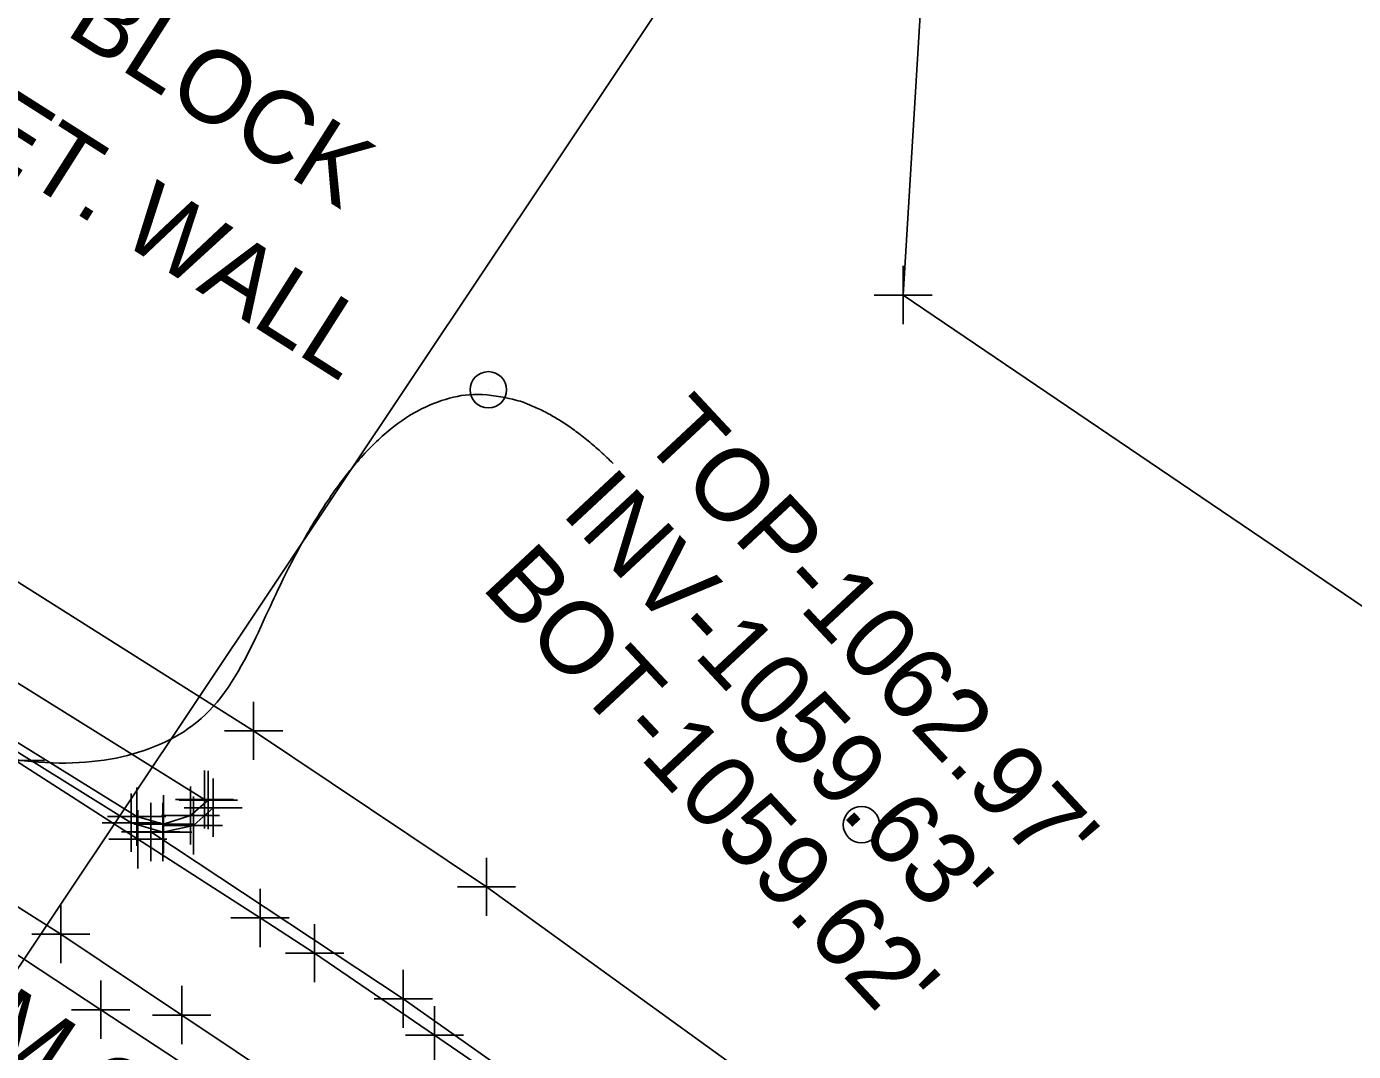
# Model space of a CAD drawing. Extents: x 0 to 1944463, y 0 to 420651.
# Drawn here: x 1942891.8 to 1942983.1, y 417799.1 to 417869.6 of the extents above; entities that cross this region are included whole.
import ezdxf

# ---------------------------------------------------------------- set-up
doc = ezdxf.new("R2010")
doc.units = 0
for name, color, linetype in [('SUR - DRG - Storm Sewer Text', 7, 'Continuous'), ('SUR - DTM - Breaklines', 7, 'Continuous'), ('SUR - DTM - Breaklines - Points - Locators', 7, 'Continuous'), ('SUR - DTM - Spot Points - Locators', 7, 'Continuous'), ('SUR - NON-TRAN - Features Text', 7, 'Continuous'), ('SUR - TR-CTRL - Pavement Marking', 7, 'Continuous'), ('SUR - TR-CTRL - Pavement Marking - Points - Locators', 7, 'Continuous'), ('SUR - TRAN - Features', 7, 'Continuous'), ('SUR - TRAN - Features - Points - Locators', 7, 'Continuous'), ('SUR - UTL - Overhead Wire Crossings', 7, 'Continuous')]:
    doc.layers.add(name, color=color, linetype=linetype)

msp = doc.modelspace()

# ---------------------------------------------------------------- linework, layer by layer
at = {"layer": 'SUR - DRG - Storm Sewer Text'}
msp.add_open_spline([(1942932.189, 417839.53), (1942918.396, 417853.168), (1942896.946, 417801.969), (1942834.043, 417852.189)], degree=2, dxfattribs=at)
at = {"layer": 'SUR - DTM - Breaklines'}
msp.add_lwpolyline([(1942904.344, 417816.385), (1942903.123, 417815.324), (1942901.264, 417814.723), (1942899.42, 417815.244), (1942882.48, 417825.759), (1942881.098, 417827.348), (1942880.664, 417829.033), (1942881.191, 417830.726)], dxfattribs=at)
at = {"layer": 'SUR - DTM - Breaklines - Points - Locators'}
for p, q in [((1942904.344, 417816.385), (1942904.344, 417818.385)), ((1942899.42, 417815.244), (1942899.42, 417817.244)), ((1942903.123, 417815.324), (1942903.123, 417817.324)), ((1942901.264, 417814.723), (1942901.264, 417816.723)), ((1942904.344, 417816.385), (1942902.344, 417816.385)), ((1942904.344, 417816.385), (1942906.344, 417816.385)), ((1942904.344, 417816.385), (1942904.344, 417814.385)), ((1942899.42, 417815.244), (1942897.42, 417815.244)), ((1942899.42, 417815.244), (1942901.42, 417815.244)), ((1942899.42, 417815.244), (1942899.42, 417813.244)), ((1942903.123, 417815.324), (1942901.123, 417815.324)), ((1942903.123, 417815.324), (1942905.123, 417815.324)), ((1942903.123, 417815.324), (1942903.123, 417813.324)), ((1942901.264, 417814.723), (1942899.264, 417814.723)), ((1942901.264, 417814.723), (1942903.264, 417814.723)), ((1942901.264, 417814.723), (1942901.264, 417812.723))]:
    msp.add_line(p, q, dxfattribs=at)
at = {"layer": 'SUR - DTM - Spot Points - Locators'}
for p, q in [((1942923.623, 417844.584), (1942923.623, 417844.584)), ((1942949.287, 417814.681), (1942949.287, 417814.681))]:
    msp.add_line(p, q, dxfattribs=at)
for centre in [(1942923.612, 417844.595), (1942949.276, 417814.691)]:
    msp.add_circle(centre, 1.25, dxfattribs=at)
at = {"layer": 'SUR - TR-CTRL - Pavement Marking'}
for points in [[(1942891.086, 417819.102), (1942899.495, 417813.69), (1942907.904, 417808.278), (1942911.658, 417805.861), (1942919.906, 417800.207), (1942928.154, 417794.552), (1942928.314, 417794.443), (1942936.461, 417788.644), (1942944.609, 417782.845), (1942947.69, 417780.653), (1942955.664, 417774.619), (1942963.639, 417768.585), (1942969.488, 417764.159), (1942977.356, 417757.986), (1942985.223, 417751.814), (1942986.298, 417750.97), (1942993.949, 417744.53), (1943001.599, 417738.09), (1943007.774, 417732.892), (1943015.425, 417726.452)], [(1942888.586, 417807.457), (1942896.946, 417801.969), (1942905.305, 417796.481), (1942910.263, 417793.226), (1942918.458, 417787.496), (1942926.654, 417781.766), (1942931.271, 417778.538), (1942939.324, 417772.609), (1942947.377, 417766.681), (1942952.498, 417762.911), (1942960.396, 417756.776), (1942968.293, 417750.642), (1942969.893, 417749.399), (1942977.615, 417743.047), (1942985.338, 417736.694), (1942991.977, 417731.232), (1942999.466, 417724.605), (1943006.955, 417717.978), (1943010.255, 417715.058), (1943017.621, 417708.294), (1943023.187, 417703.184), (1943030.403, 417696.261), (1943037.62, 417689.339), (1943043.714, 417683.493)]]:
    msp.add_lwpolyline(points, dxfattribs=at)
at = {"layer": 'SUR - TR-CTRL - Pavement Marking - Points - Locators'}
for p, q in [((1942891.086, 417819.102), (1942893.086, 417819.102)), ((1942899.495, 417813.69), (1942899.495, 417815.69)), ((1942899.495, 417813.69), (1942897.495, 417813.69)), ((1942899.495, 417813.69), (1942901.495, 417813.69)), ((1942899.495, 417813.69), (1942899.495, 417811.69)), ((1942907.904, 417808.278), (1942907.904, 417810.278)), ((1942907.904, 417808.278), (1942905.904, 417808.278)), ((1942907.904, 417808.278), (1942909.904, 417808.278)), ((1942907.904, 417808.278), (1942907.904, 417806.278)), ((1942911.658, 417805.861), (1942911.658, 417807.861)), ((1942911.658, 417805.861), (1942909.658, 417805.861)), ((1942911.658, 417805.861), (1942913.658, 417805.861)), ((1942911.658, 417805.861), (1942911.658, 417803.861)), ((1942896.946, 417801.969), (1942896.946, 417803.969)), ((1942896.946, 417801.969), (1942894.946, 417801.969)), ((1942896.946, 417801.969), (1942898.946, 417801.969)), ((1942896.946, 417801.969), (1942896.946, 417799.969)), ((1942919.906, 417800.207), (1942919.906, 417802.207)), ((1942919.906, 417800.207), (1942917.906, 417800.207)), ((1942919.906, 417800.207), (1942921.906, 417800.207)), ((1942919.906, 417800.207), (1942919.906, 417798.207))]:
    msp.add_line(p, q, dxfattribs=at)
at = {"layer": 'SUR - TRAN - Features'}
for p, q in [((1942894.204, 417807.16), (1942894.204, 417809.16)), ((1942894.204, 417807.16), (1942892.204, 417807.16)), ((1942894.204, 417807.16), (1942896.204, 417807.16)), ((1942894.204, 417807.16), (1942894.204, 417805.16)), ((1942902.517, 417801.602), (1942902.517, 417803.602)), ((1942902.517, 417801.602), (1942900.517, 417801.602)), ((1942902.517, 417801.602), (1942904.517, 417801.602)), ((1942902.517, 417801.602), (1942902.517, 417799.602))]:
    msp.add_line(p, q, dxfattribs=at)
for points in [[(1943114.834, 417624.896), (1943103.453, 417639.126), (1943095.3, 417651.485), (1943083.428, 417672.654), (1943076.721, 417682.249), (1943055.252, 417704.387), (1943020.966, 417735.536), (1942996.784, 417756.051), (1942978.451, 417770.697), (1942923.479, 417810.417), (1942907.463, 417821.141), (1942884.283, 417835.758), (1942865.83, 417846.651), (1942848.31, 417856.509), (1942835.5, 417863.859), (1942826.295, 417870.821), (1942818.403, 417877.862), (1942796.294, 417899.443), (1942790.861, 417907.343), (1942782.321, 417924.544), (1942774.775, 417947.78), (1942772.79, 417958.555), (1942771.547, 417970.782), (1942773.585, 418011.209)], [(1943002.665, 417751.274), (1943031.879, 417794.998), (1942996.657, 417820.965), (1942952.147, 417851.111), (1942954.099, 417883.232)], [(1942904.684, 417815.858), (1942903.329, 417814.639), (1942901.207, 417814.187), (1942899.048, 417814.828), (1942882.167, 417825.323), (1942880.524, 417827.215), (1942880.142, 417828.976), (1942880.734, 417831.122)], [(1942904.08, 417816.419), (1942881.26, 417830.645)], [(1942937.538, 417788.752), (1942917.758, 417802.719), (1942900.381, 417814.193)], [(1942886.414, 417812.085), (1942894.204, 417807.16), (1942902.517, 417801.602), (1942910.007, 417796.595), (1942918.232, 417790.907), (1942924.506, 417786.568), (1942932.64, 417780.752), (1942939.682, 417775.718), (1942947.702, 417769.745), (1942955.722, 417763.771), (1942960.116, 417760.499), (1942967.95, 417754.283), (1942973.293, 417750.043), (1942981.017, 417743.692), (1942988.741, 417737.341), (1942990.258, 417736.093), (1942997.88, 417729.619), (1943005.501, 417723.144)]]:
    msp.add_lwpolyline(points, dxfattribs=at)
at = {"layer": 'SUR - TRAN - Features - Points - Locators'}
for p, q in [((1942952.147, 417851.111), (1942952.147, 417853.111)), ((1942952.147, 417851.111), (1942950.147, 417851.111)), ((1942952.147, 417851.111), (1942954.147, 417851.111)), ((1942952.147, 417851.111), (1942952.147, 417849.111)), ((1942907.463, 417821.141), (1942907.463, 417823.141)), ((1942907.463, 417821.141), (1942905.463, 417821.141)), ((1942907.463, 417821.141), (1942909.463, 417821.141)), ((1942907.463, 417821.141), (1942907.463, 417819.141)), ((1942904.08, 417816.419), (1942904.08, 417818.419)), ((1942904.684, 417815.858), (1942904.684, 417817.858)), ((1942899.048, 417814.828), (1942899.048, 417816.828)), ((1942900.381, 417814.193), (1942900.381, 417816.193)), ((1942901.207, 417814.187), (1942901.207, 417816.187)), ((1942904.08, 417816.419), (1942902.08, 417816.419)), ((1942903.329, 417814.639), (1942903.329, 417816.639)), ((1942904.08, 417816.419), (1942906.08, 417816.419)), ((1942904.08, 417816.419), (1942904.08, 417814.419)), ((1942904.684, 417815.858), (1942902.684, 417815.858)), ((1942904.684, 417815.858), (1942906.684, 417815.858)), ((1942904.684, 417815.858), (1942904.684, 417813.858)), ((1942899.048, 417814.828), (1942897.048, 417814.828)), ((1942899.048, 417814.828), (1942901.048, 417814.828)), ((1942899.048, 417814.828), (1942899.048, 417812.828)), ((1942903.329, 417814.639), (1942901.329, 417814.639)), ((1942903.329, 417814.639), (1942905.329, 417814.639)), ((1942903.329, 417814.639), (1942903.329, 417812.639)), ((1942900.381, 417814.193), (1942898.381, 417814.193)), ((1942901.207, 417814.187), (1942899.207, 417814.187)), ((1942900.381, 417814.193), (1942902.381, 417814.193)), ((1942900.381, 417814.193), (1942900.381, 417812.193)), ((1942901.207, 417814.187), (1942903.207, 417814.187)), ((1942901.207, 417814.187), (1942901.207, 417812.187)), ((1942923.479, 417810.417), (1942923.479, 417812.417)), ((1942923.479, 417810.417), (1942921.479, 417810.417)), ((1942923.479, 417810.417), (1942925.479, 417810.417)), ((1942923.479, 417810.417), (1942923.479, 417808.417)), ((1942917.758, 417802.719), (1942917.758, 417804.719)), ((1942917.758, 417802.719), (1942915.758, 417802.719)), ((1942917.758, 417802.719), (1942919.758, 417802.719)), ((1942917.758, 417802.719), (1942917.758, 417800.719))]:
    msp.add_line(p, q, dxfattribs=at)
at = {"layer": 'SUR - UTL - Overhead Wire Crossings'}
msp.add_lwpolyline([(1942849.572, 417742.451), (1942957.655, 417904.238)], dxfattribs=at)

# ---------------------------------------------------------------- texts
at = {"layer": 'SUR - DRG - Storm Sewer Text'}
for s, rotation, p in [("TOP-1062.97'", 313, (1942934.017, 417841.235)), ("INV-1059.63'", 313, (1942928.532, 417836.12)), ("BOT-1059.62'", 313, (1942923.047, 417831.005)), ('INVERTS FROM CONST. PLANS', 326.50837, (1942850.783, 417824.362)), ('INACCESSIBLE COVERED JUNCTION', 326.50837, (1942834.765, 417816.974)), ('APPROX. LOCATION ', 326.50837, (1942862.43, 417807.662))]:
    msp.add_text(s, height=4.99999, rotation=rotation, dxfattribs=at).set_placement(p)
at = {"layer": 'SUR - NON-TRAN - Features Text'}
for s, p in [('BLOCK ', (1942894.403, 417869.098)), ('RET. WALL', (1942883.68, 417864.065))]:
    msp.add_text(s, height=5, rotation=327.55481, dxfattribs=at).set_placement(p)

doc.saveas('drawing.dxf')
